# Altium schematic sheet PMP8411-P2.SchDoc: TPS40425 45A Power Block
size 431 x 279 mm; VersionControl_RevNumber: REV B; Date: Not shown in title block; ApprovedBy: Not shown in title block; CheckedBy: Not shown in title block; Author: Not shown in title block; CompanyName: Not shown in title block; DrawnBy: Tiger Zhou; Organization: Not shown in title block; Address1: Not shown in title block; Address2: Not shown in title block; Address3: Not shown in title block; Address4: Not shown in title block; DocumentNumber: 1; Revision: Use project parameter SCH_Rev; SheetNumber: 2; SheetTotal: 3; PageSetup: Record=PageOptions¦CenterHorizontal=True¦CenterVertical=True¦PrintScale=0.64¦XCorrection=1.00¦YCorrection=1.00¦PrintKind=0¦BorderSize=5000000¦LeftOffset=0¦BottomOffset=0¦Orientation=2¦PaperLength=1000¦PaperWidth=1000¦Scale=100¦PaperSource=15¦PrintQuality=600¦MediaType=1¦DitherType=10¦PrintScaleMode=1¦PaperKind=Letter
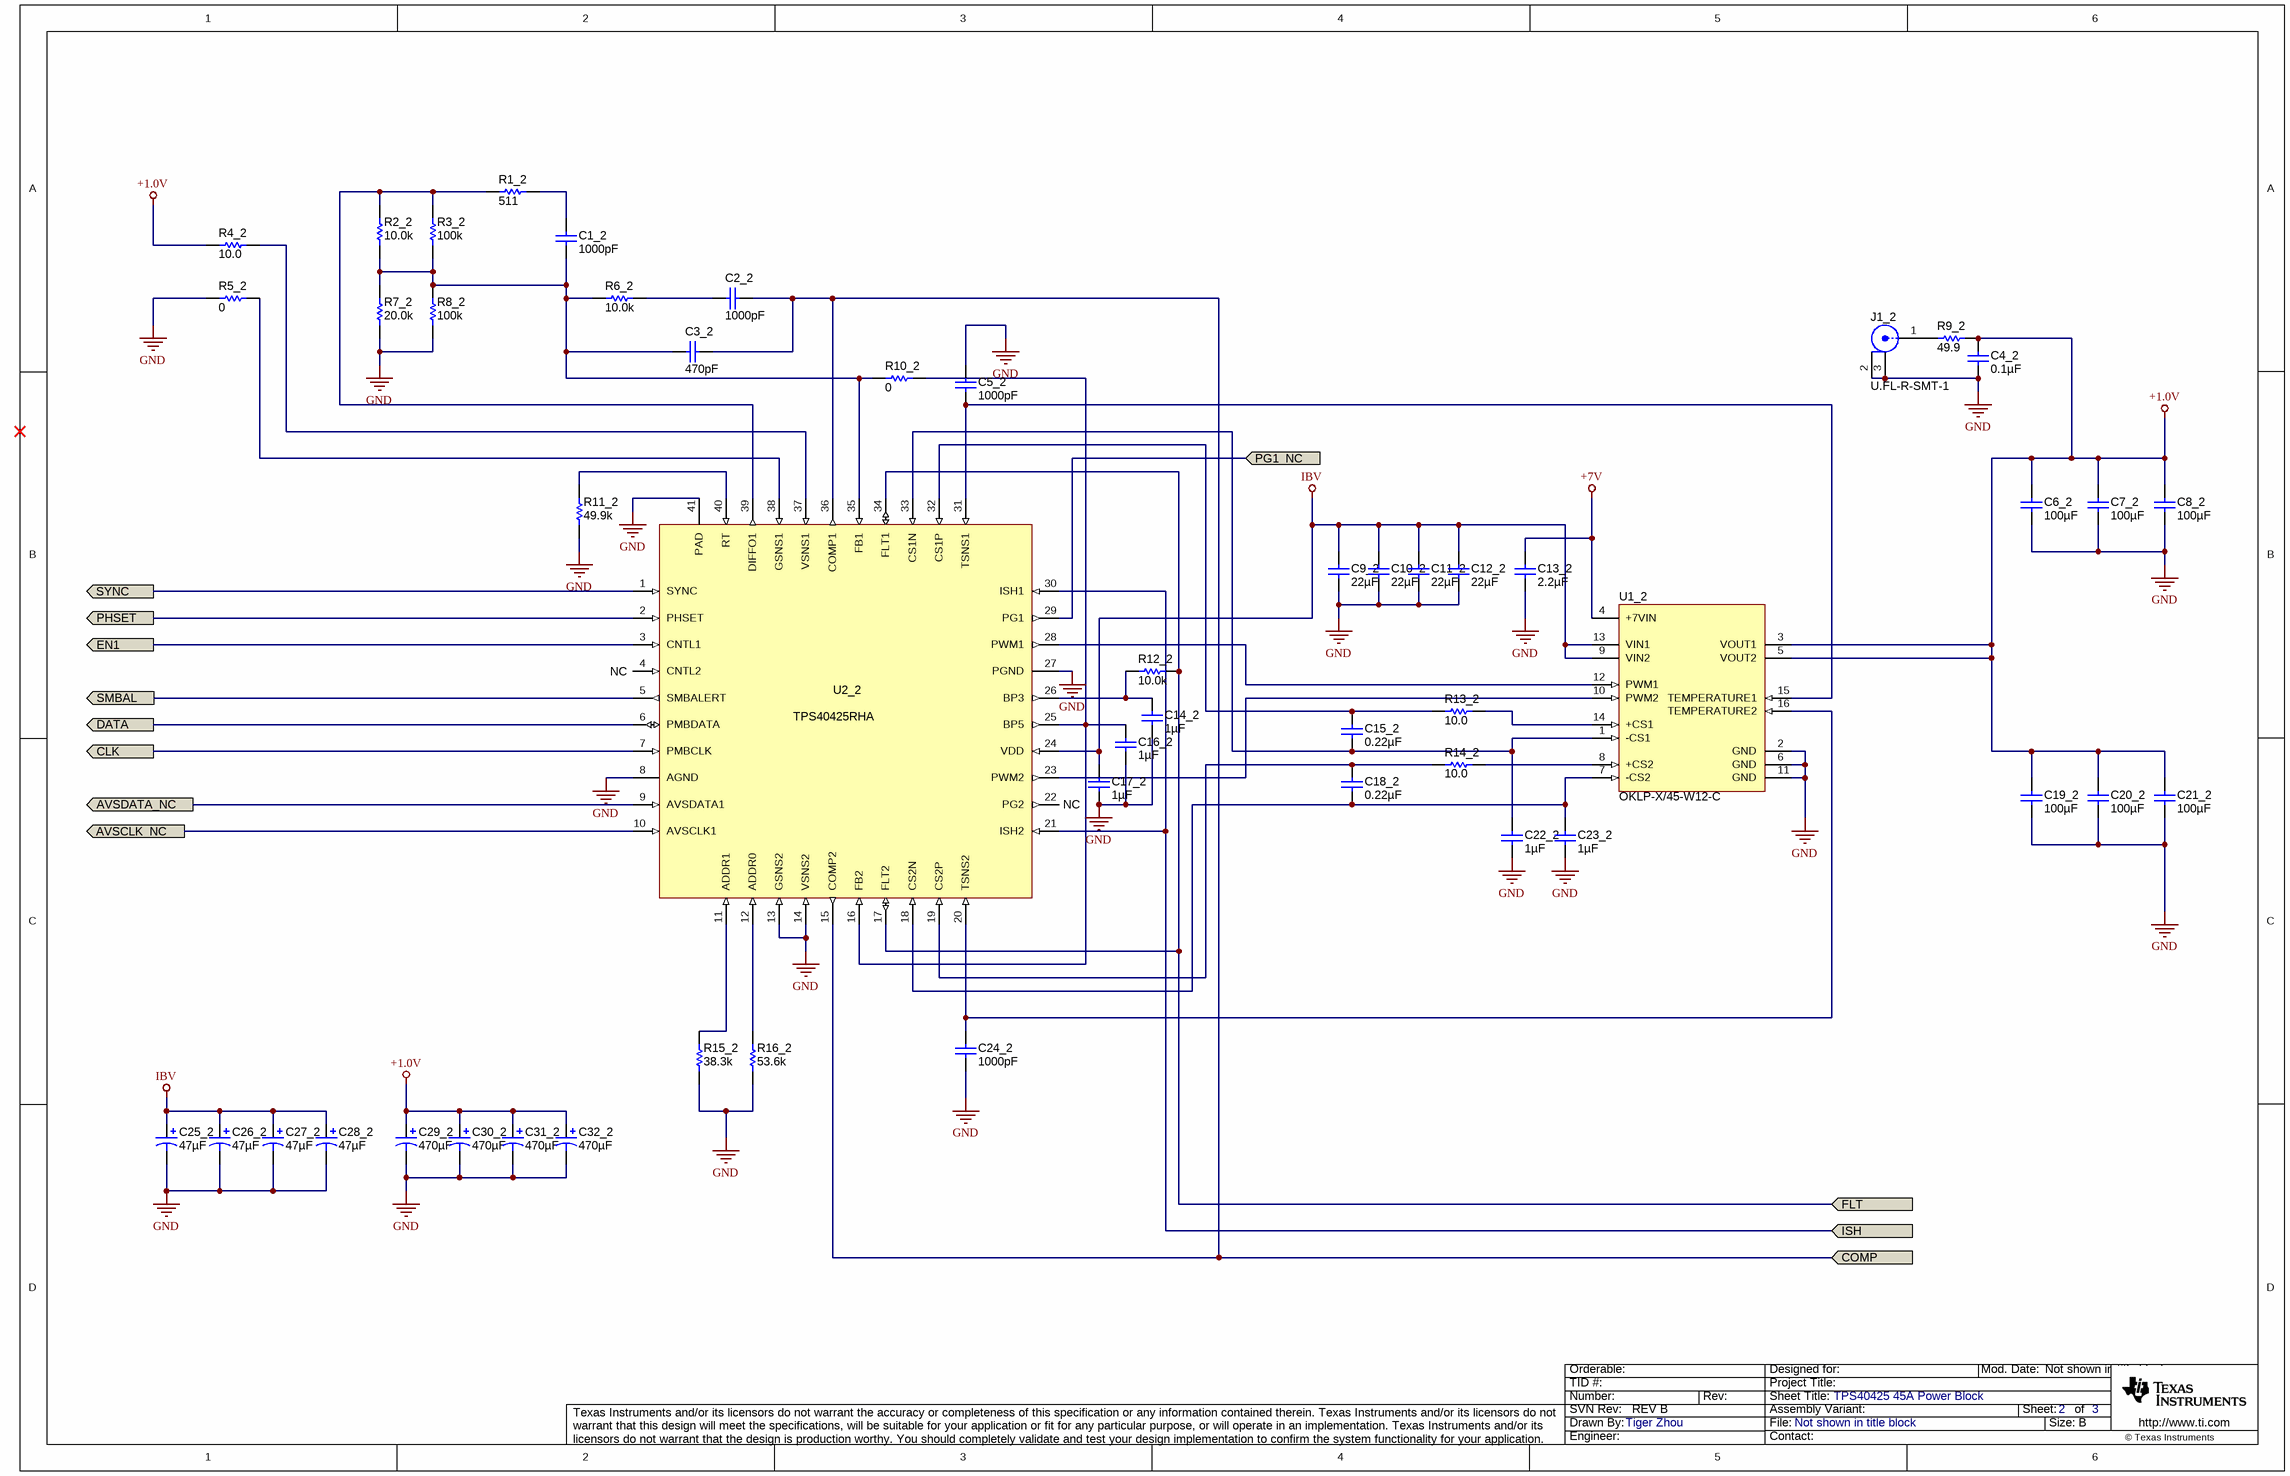
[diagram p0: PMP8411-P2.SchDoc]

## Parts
C1_2  ValueDisplayed: 1000pF  [0402S]  (hidden comment: C1005C0G1E102J)
C2_2  ValueDisplayed: 1000pF  [0402S]  (hidden comment: C1005C0G1E102J)
C3_2  ValueDisplayed: 470pF  [0402S]  (hidden comment: C1005C0G1H471J)
C4_2  ValueDisplayed: 0.1µF  [0402S]  (hidden comment: C1005X7R1H104K)
C5_2  ValueDisplayed: 1000pF  [0402S]  (hidden comment: C1005C0G1E102J)
C6_2  ValueDisplayed: 100µF  [1210]  (hidden comment: GRM32EC80J107ME20L)
C7_2  ValueDisplayed: 100µF  [1210]  (hidden comment: GRM32EC80J107ME20L)
C8_2  ValueDisplayed: 100µF  [1210]  (hidden comment: GRM32EC80J107ME20L)
C9_2  ValueDisplayed: 22µF  [1210]  (hidden comment: GRM32ER61C226KE20L)
C10_2  ValueDisplayed: 22µF  [1210]  (hidden comment: GRM32ER61C226KE20L)
C11_2  ValueDisplayed: 22µF  [1210]  (hidden comment: GRM32ER61C226KE20L)
C12_2  ValueDisplayed: 22µF  [1210]  (hidden comment: GRM32ER61C226KE20L)
C13_2  ValueDisplayed: 2.2µF  [0603S]  (hidden comment: GRM188R61C225KAAD)
C14_2  ValueDisplayed: 1µF  [0603S]  (hidden comment: C1608X5R1E105K080AC)
C15_2  ValueDisplayed: 0.22µF  [0402S]  (hidden comment: C1005X7R1C224K050BC)
C16_2  ValueDisplayed: 1µF  [0603S]  (hidden comment: C1608X5R1E105K080AC)
C17_2  ValueDisplayed: 1µF  [0603S]  (hidden comment: C1608X5R1E105K080AC)
C18_2  ValueDisplayed: 0.22µF  [0402S]  (hidden comment: C1005X7R1C224K050BC)
C19_2  ValueDisplayed: 100µF  [1210]  (hidden comment: GRM32EC80J107ME20L)
C20_2  ValueDisplayed: 100µF  [1210]  (hidden comment: GRM32EC80J107ME20L)
C21_2  ValueDisplayed: 100µF  [1210]  (hidden comment: GRM32EC80J107ME20L)
C22_2  ValueDisplayed: 1µF  [0402S]  (hidden comment: C1005X5R0J105M)
C23_2  ValueDisplayed: 1µF  [0402S]  (hidden comment: C1005X5R0J105M)
C24_2  ValueDisplayed: 1000pF  [0402S]  (hidden comment: C1005C0G1E102J)
C25_2  ValueDisplayed: 47µF  [7343-31]  (hidden comment: TPSD476M016R0080)
C26_2  ValueDisplayed: 47µF  [7343-31]  (hidden comment: TPSD476M016R0080)
C27_2  ValueDisplayed: 47µF  [7343-31]  (hidden comment: TPSD476M016R0080)
C28_2  ValueDisplayed: 47µF  [7343-31]  (hidden comment: TPSD476M016R0080)
C29_2  ValueDisplayed: 470µF  [CAPSMT_6_D3L]  (hidden comment: 4TPE470MAL)
C30_2  ValueDisplayed: 470µF  [CAPSMT_6_D3L]  (hidden comment: 4TPE470MAL)
C31_2  ValueDisplayed: 470µF  [CAPSMT_6_D3L]  (hidden comment: 4TPE470MAL)
C32_2  ValueDisplayed: 470µF  [CAPSMT_6_D3L]  (hidden comment: 4TPE470MAL)
J1_2  U.FL-R-SMT-1  [CONN_UFL-R-SMT-1]
R1_2  ValueDisplayed: 511  [0402S]  (hidden comment: CRCW0402511RFKED)
R2_2  ValueDisplayed: 10.0k  [0402S]  (hidden comment: PCF0402-12-10KBT1)
R3_2  ValueDisplayed: 100k  [0402S]  (hidden comment: CRCW0402100KFKED)
R4_2  ValueDisplayed: 10.0  [0402S]  (hidden comment: CRCW040210R0FKED)
R5_2  ValueDisplayed: 0  [0402S]  (hidden comment: ERJ-2GE0R00X)
R6_2  ValueDisplayed: 10.0k  [0402S]  (hidden comment: CRCW040210K0FKED)
R7_2  ValueDisplayed: 20.0k  [0402S]  (hidden comment: CRCW040220K0FKED)
R8_2  ValueDisplayed: 100k  [0402S]  (hidden comment: CRCW0402100KFKED)
R9_2  ValueDisplayed: 49.9  [0402S]  (hidden comment: CRCW040249R9FKED)
R10_2  ValueDisplayed: 0  [0402S]  (hidden comment: ERJ-2GE0R00X)
R11_2  ValueDisplayed: 49.9k  [0402S]  (hidden comment: CRCW040249K9FKED)
R12_2  ValueDisplayed: 10.0k  [0402S]  (hidden comment: PCF0402-12-10KBT1)
R13_2  ValueDisplayed: 10.0  [0402S]  (hidden comment: CRCW040210R0FKED)
R14_2  ValueDisplayed: 10.0  [0402S]  (hidden comment: CRCW040210R0FKED)
R15_2  ValueDisplayed: 38.3k  [0402S]  (hidden comment: CRCW040238K3FKED)
R16_2  ValueDisplayed: 53.6k  [0402S]  (hidden comment: CRCW040253K6FKED)
U1_2  OKLP-X/45-W12-C  [OKLP-X_45-W12-C]
U2_2  TPS40425RHA  [RHA0040B]

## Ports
AVSCLK_NC, AVSDATA_NC, CLK, COMP, DATA, EN1, FLT, ISH, PG1_NC, PHSET, SMBAL, SYNC

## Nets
+1.0V: C4_2.1 C6_2.1 C7_2.1 C8_2.1 C19_2.1 C20_2.1 C21_2.1 C29_2.1(+) C30_2.1(+) C31_2.1(+) C32_2.1(+) R4_2.1 R9_2.2 U1_2.3(VOUT1) U1_2.5(VOUT2)
+7V: C13_2.1 U1_2.4(+7VIN)
GND: C4_2.2 C5_2.1 C6_2.2 C7_2.2 C8_2.2 C9_2.2 C10_2.2 C11_2.2 C12_2.2 C13_2.2 C14_2.2 C16_2.2 C17_2.2 C19_2.2 C20_2.2 C21_2.2 C22_2.2 C23_2.2 C24_2.2 C25_2.2(-) C26_2.2(-) C27_2.2(-) C28_2.2(-) C29_2.2(-) C30_2.2(-) C31_2.2(-) C32_2.2(-) J1_2.2 J1_2.3 R5_2.1 R7_2.1 R8_2.1 R11_2.1 R15_2.1 R16_2.1 U1_2.2(GND) U1_2.6(GND) U1_2.11(GND) U2_2.8(AGND) U2_2.13(GSNS2) U2_2.14(VSNS2) U2_2.27(PGND) U2_2.41(PAD)
IBV: C9_2.1 C10_2.1 C11_2.1 C12_2.1 C17_2.1 C25_2.1(+) C26_2.1(+) C27_2.1(+) C28_2.1(+) U1_2.9(VIN2) U1_2.13(VIN1) U2_2.24(VDD)
AVSCLK_NC: U2_2.10(AVSCLK1) ; port AVSCLK_NC
AVSDATA_NC: U2_2.9(AVSDATA1) ; port AVSDATA_NC
CLK: U2_2.7(PMBCLK) ; port CLK
COMP: C2_2.1 C3_2.1 U2_2.15(COMP2) U2_2.36(COMP1) ; port COMP
DATA: U2_2.6(PMBDATA) ; port DATA
EN1: U2_2.3(CNTL1) ; port EN1
FLT: R12_2.1 U2_2.17(FLT2) U2_2.34(FLT1) ; port FLT
ISH: U2_2.21(ISH2) U2_2.30(ISH1) ; port ISH
PG1_NC: U2_2.29(PG1) ; port PG1_NC
PHSET: U2_2.2(PHSET) ; port PHSET
SMBAL: U2_2.5(SMBALERT) ; port SMBAL
SYNC: U2_2.1(SYNC) ; port SYNC
NetC1_2_1: C1_2.1 R1_2.2
NetC1_2_2: C1_2.2 C3_2.2 R2_2.1 R3_2.1 R6_2.1 R7_2.2 R8_2.2 R10_2.1 U2_2.35(FB1)
NetC2_2_2: C2_2.2 R6_2.2
NetC5_2_2: C5_2.2 U1_2.15(TEMPERATURE1) U2_2.31(TSNS1)
NetC14_2_1: C14_2.1 R12_2.2 U2_2.26(BP3)
NetC15_2_1: C15_2.1 R13_2.1 U2_2.32(CS1P)
NetC15_2_2: C15_2.2 C22_2.1 U1_2.1(-CS1) U2_2.33(CS1N)
NetC16_2_1: C16_2.1 R10_2.2 U2_2.16(FB2) U2_2.25(BP5)
NetC18_2_1: C18_2.1 R14_2.1 U2_2.19(CS2P)
NetC18_2_2: C18_2.2 C23_2.1 U1_2.7(-CS2) U2_2.18(CS2N)
NetC24_2_1: C24_2.1 U1_2.16(TEMPERATURE2) U2_2.20(TSNS2)
NetJ1_2_1: J1_2.1 R9_2.1
NetR1_2_1: R1_2.1 R2_2.2 R3_2.2 U2_2.39(DIFFO1)
NetR4_2_2: R4_2.2 U2_2.37(VSNS1)
NetR5_2_2: R5_2.2 U2_2.38(GSNS1)
NetR11_2_2: R11_2.2 U2_2.40(RT)
NetR13_2_2: R13_2.2 U1_2.14(+CS1)
NetR14_2_2: R14_2.2 U1_2.8(+CS2)
NetR15_2_2: R15_2.2 U2_2.11(ADDR1)
NetR16_2_2: R16_2.2 U2_2.12(ADDR0)
NetU1_2_10: U1_2.10(PWM2) U2_2.23(PWM2)
NetU1_2_12: U1_2.12(PWM1) U2_2.28(PWM1)

Not connected (* = marked no-connect by the designer): U2_2 4(CNTL2) 22(PG2)

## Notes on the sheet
- (near U2_2) NC
- NC

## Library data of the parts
C1_2 C2_2 C5_2 C24_2 = C1005C0G1E102J: CAP, CERM, 1000 pF, 25 V, +/- 5%, C0G/NP0, 0402; Manufacturer: TDK; Polarized: N; CompType: Capacitor; Value: 1000pF; U/M: EA; Cap_F: 0.000000001; Tolerance_%: 5; Value1: Unknown; VDC_V: 25; Value2: 25V; TaMin_C: -55; TaMax_C: 125; Cap_Case: 0402
C3_2 = C1005C0G1H471J: CAP, CERM, 470 pF, 50 V, +/- 5%, C0G/NP0, 0402; Manufacturer: TDK; Polarized: N; CompType: Capacitor; Value: 470pF; U/M: EA; Cap_F: 0.00000000047; Tolerance_%: 5; ESR_ohm: 0.0788; Value1: 0.0788 ohm; VDC_V: 50; Value2: 50V; TaMin_C: -55; TaMax_C: 125; Cap_Case: 0402
C4_2 = C1005X7R1H104K: CAP, CERM, 0.1 µF, 50 V, +/- 10%, C0G/NP0, 0402; Manufacturer: TDK; Polarized: N; CompType: Capacitor; Value: 0.1uF; U/M: EA; Cap_F: 0.0000001; Tolerance_%: 10; Value1: Unknown; VDC_V: 50; Value2: 50V; TaMin_C: -55; TaMax_C: 125; Cap_Case: 0402
C6_2 C7_2 C8_2 C19_2 C20_2 C21_2 = GRM32EC80J107ME20L: CAP, CERM, 100 µF, 6.3 V, +/- 20%, X6S, 1210; Manufacturer: MuRata; Polarized: N; CompType: Capacitor; Value: 100uF; U/M: EA; Cap_F: 0.0001; Tolerance_%: 20; Value1: Unknown; VDC_V: 6.3; Value2: 6.3V; TaMin_C: -55; TaMax_C: 105
C9_2 C10_2 C11_2 C12_2 = GRM32ER61C226KE20L: CAP, CERM, 22 µF, 16 V, +/- 10%, X5R, 1210; Manufacturer: MuRata; Polarized: N; CompType: Capacitor; Value: 22uF; U/M: EA; Cap_F: 0.000022; Tolerance_%: 10; ESR_ohm: 0.002; Value1: 0.002 ohm; VDC_V: 16; Value2: 16V; IRMS_A: 3.68; TaMin_C: -55; TaMax_C: 85
C13_2 = GRM188R61C225KAAD: CAP, CERM, 2.2 µF, 16 V, +/- 10%, X5R, 0603; Manufacturer: MuRata; Polarized: N; CompType: Capacitor; Value: 2.2uF; U/M: EA; Cap_F: 0.0000022; Tolerance_%: 10; Value1: Unknown; VDC_V: 16; Value2: 16V; TaMin_C: -55; TaMax_C: 85; Cap_Case: 0603
C14_2 C16_2 C17_2 = C1608X5R1E105K080AC: CAP, CERM, 1 µF, 25 V, +/- 10%, X5R, 0603; Manufacturer: TDK; Polarized: N; CompType: Capacitor; Value: 1uF; U/M: EA; Cap_F: 0.000001; Tolerance_%: 10; Value1: Unknown; VDC_V: 25; Value2: 25V; TaMin_C: -55; TaMax_C: 85; Cap_Case: 0603
C15_2 C18_2 = C1005X7R1C224K050BC: CAP, CERM, 0.22 µF, 16 V, +/- 10%, X7R, 0402; Manufacturer: TDK; Polarized: N; CompType: Capacitor; Value: 0.22uF; U/M: EA; Cap_F: 0.00000022; Tolerance_%: 10; Value1: Unknown; VDC_V: 16; Value2: 16V; TaMin_C: -55; TaMax_C: 125; Cap_Case: 0402
C22_2 C23_2 = C1005X5R0J105M: CAP, CERM, 1 µF, 6.3 V, +/- 20%, X5R, 0402; Manufacturer: TDK; Polarized: N; CompType: Capacitor; Value: 1uF; U/M: EA; Cap_F: 0.000001; Tolerance_%: 20; ESR_ohm: 0.0079; Value1: 0.0079 ohm; VDC_V: 6.3; Value2: 6.3V; TaMin_C: -55; TaMax_C: 85; Cap_Case: 0402
C25_2 C26_2 C27_2 C28_2 = TPSD476M016R0080: CAP, TA, 47 µF, 16 V, +/- 20%, 0.08 ohm, SMD; Manufacturer: AVX; Polarized: Y; CompType: Capacitor; Value: 47uF; U/M: EA; Cap_F: 0.000047; Tolerance_%: 20; VDC_V: 16; Value2: 16V; ESR_ohm: 0.08; IRMS_A: 1.232; TaMin_C: -55; TaMax_C: 125; Cap_Case: D
C29_2 C30_2 C31_2 C32_2 = 4TPE470MAL: CAP, TA, 470 µF, 4 V, +/- 20%, 0.01 ohm, SMD; Manufacturer: Panasonic; Polarized: Y; CompType: Capacitor; Value: 470uF; U/M: EA; Cap_F: 0.00047; Tolerance_%: 20; VDC_V: 4; Value2: 4V; ESR_ohm: 0.01; IRMS_A: 4.4; TaMin_C: -55; TaMax_C: 105; Cap_Case: D3L
J1_2 = U.FL-R-SMT-1: Connector, Ultra-Mini Coaxial, SMD; Manufacturer: Hirose Electric Co. Ltd.; SymbolCreator: a0412235; U/M: EA
R1_2 = CRCW0402511RFKED: RES, 511, 1%, 0.063 W, 0402; Manufacturer: Vishay-Dale; CompType: Resistor; Value: 511; Value_Code: 511R; Tolerance_%: 1; Power_W: 0.063; Value2: 0.063W; VDC_V: 50; TempCo: 100 ppm/C; EIA_Code: E96; U/M: EA
R2_2 R12_2 = PCF0402-12-10KBT1: RES, 10.0 k, 0.1%, 0.063 W, 0402; Manufacturer: TT Electronics/IRC; CompType: Resistor; Value: 10.0k; Res_ohm: 10000; Value_Code: 10k0; Tolerance_%: 0.1; Power_W: 0.063; Value2: 0.063W; VDC_V: 25; TempCo: 10 ppm/C; EIA_Code: E192; U/M: EA
R3_2 R8_2 = CRCW0402100KFKED: RES, 100 k, 1%, 0.063 W, 0402; Manufacturer: Vishay-Dale; CompType: Resistor; Value: 100k; Res_ohm: 100000; Tolerance_%: 1; Power_W: 0.063; Value2: 0.063W; VDC_V: 50; TempCo: 100 ppm/C; EIA_Code: E96; U/M: EA
R4_2 R13_2 R14_2 = CRCW040210R0FKED: RES, 10.0, 1%, 0.063 W, 0402; Manufacturer: Vishay-Dale; CompType: Resistor; Value: 10.0; Res_ohm: 10; Value_Code: 10R0; Tolerance_%: 1; Power_W: 0.063; Value2: 0.063W; VDC_V: 50; TempCo: 100 ppm/C; EIA_Code: E96; U/M: EA
R5_2 R10_2 = ERJ-2GE0R00X: RES, 0, 5%, 0.063 W, 0402; Manufacturer: Panasonic; CompType: Resistor; Value: 0; Value_Code: 0000; Tolerance_%: 5; Power_W: 0.063; Value2: 0.063W; VDC_V: 50; TempCo: 600 ppm/C; EIA_Code: E24; U/M: EA
R6_2 = CRCW040210K0FKED: RES, 10.0 k, 1%, 0.063 W, 0402; Manufacturer: Vishay-Dale; CompType: Resistor; Value: 10.0k; Res_ohm: 10000; Value_Code: 10k0; Tolerance_%: 1; Power_W: 0.063; Value2: 0.063W; VDC_V: 50; TempCo: 100 ppm/C; EIA_Code: E96; U/M: EA
R7_2 = CRCW040220K0FKED: RES, 20.0 k, 1%, 0.063 W, 0402; Manufacturer: Vishay-Dale; CompType: Resistor; Value: 20.0k; Res_ohm: 20000; Value_Code: 20k0; Tolerance_%: 1; Power_W: 0.063; Value2: 0.063W; VDC_V: 50; TempCo: 100 ppm/C; EIA_Code: E96; U/M: EA
R9_2 = CRCW040249R9FKED: RES, 49.9, 1%, 0.063 W, 0402; Manufacturer: Vishay-Dale; CompType: Resistor; Value: 49.9; Value_Code: 49R9; Tolerance_%: 1; Power_W: 0.063; Value2: 0.063W; VDC_V: 50; TempCo: 100 ppm/C; EIA_Code: E96; U/M: EA
R11_2 = CRCW040249K9FKED: RES, 49.9 k, 1%, 0.063 W, 0402; Manufacturer: Vishay-Dale; CompType: Resistor; Value: 49.9k; Res_ohm: 49900; Value_Code: 49k9; Tolerance_%: 1; Power_W: 0.063; Value2: 0.063W; VDC_V: 50; TempCo: 100 ppm/C; EIA_Code: E96; U/M: EA
R15_2 = CRCW040238K3FKED: RES, 38.3 k, 1%, 0.063 W, 0402; Manufacturer: Vishay-Dale; CompType: Resistor; Value: 38.3k; Res_ohm: 38300; Value_Code: 38k3; Tolerance_%: 1; Power_W: 0.063; Value2: 0.063W; VDC_V: 50; TempCo: 100 ppm/C; EIA_Code: E96; U/M: EA
R16_2 = CRCW040253K6FKED: RES, 53.6 k, 1%, 0.063 W, 0402; Manufacturer: Vishay-Dale; CompType: Resistor; Value: 53.6k; Res_ohm: 53600; Value_Code: 53k6; Tolerance_%: 1; Power_W: 0.063; Value2: 0.063W; VDC_V: 50; TempCo: 100 ppm/C; EIA_Code: E96; U/M: EA
U1_2 = OKLP-X/45-W12-C: 45A Power Block Non-Isolated DC/DC Converter, SMD, Body 25.4 x 12.7 mm; Manufacturer: MuRata; SymbolCreator: Altium
U2_2 = TPS40425RHA: Dual output, 2-Phase, Stackable PMBUS Synchronous Buck Driverless Controller with AVS Bus, RHA0040B; Alternate Manufacturer: None; Manufacturer: Texas Instruments; SymbolCreator: a0799628; CompType: IC; U/M: EA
